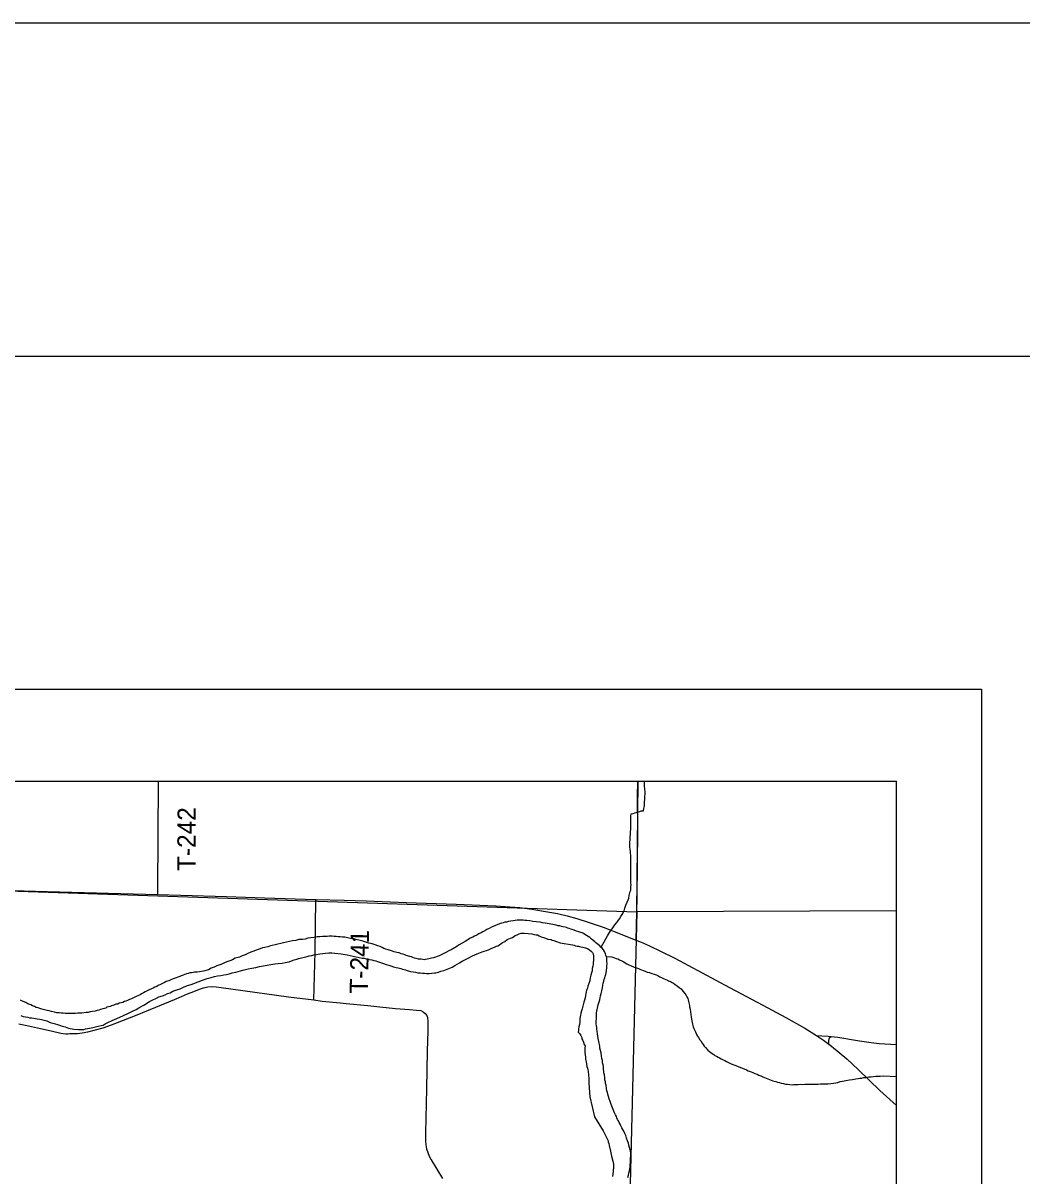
# Model space of a CAD drawing. Extents: x 0 to 68, y 0 to 52.9.
# Drawn here: x 30.062 to 31.562, y 20.269 to 22 of the extents above; entities that cross this region are included whole.
import ezdxf

# ---------------------------------------------------------------- set-up
doc = ezdxf.new("R2010")
doc.units = 0
for name, color, linetype in [('Default', 7, 'Continuous'), ('GM_X_County_Road', 7, 'Continuous'), ('GM_X_Minor_River', 7, 'Continuous'), ('GM_X_State_Route', 7, 'Continuous'), ('GM_X_Township_Road', 7, 'Continuous'), ('GM_X_Township_Road_Text', 7, 'Continuous'), ('SH_Border', 7, 'Continuous'), ('SH_Cut_Line', 7, 'Continuous'), ('SH_Data', 7, 'Continuous')]:
    doc.layers.add(name, color=color, linetype=linetype)

msp = doc.modelspace()

# ---------------------------------------------------------------- linework, layer by layer
at = {"layer": 'Default'}
for p in [(24.6206, 20.8614), (31.3735, 14.1085)]:
    msp.add_line(p, (31.3735, 20.8614), dxfattribs=at)
for points in [[(31.3735, 20.6667), (30.9835, 20.6654), (30.9859, 20.8614)], [(30.868, 20.6442), (30.8655, 20.6446), (30.8625, 20.6454), (30.86, 20.6461), (30.8574, 20.6465), (30.8548, 20.6469), (30.8519, 20.6473), (30.8493, 20.6477), (30.846, 20.6485), (30.8423, 20.6489), (30.8387, 20.6497), (30.8328, 20.6502), (30.8276, 20.651), (30.8229, 20.6518), (30.8185, 20.6522), (30.8155, 20.6526), (30.8129, 20.653), (30.8107, 20.653), (30.8089, 20.653), (30.8071, 20.6531), (30.8041, 20.6531), (30.8012, 20.6524), (30.7982, 20.6521), (30.7938, 20.6514), (30.7908, 20.6507), (30.7882, 20.65), (30.7857, 20.6497), (30.7831, 20.649), (30.7805, 20.6483), (30.7775, 20.6472), (30.7657, 20.6422), (30.762, 20.6405), (30.7583, 20.6387), (30.7557, 20.6369), (30.7527, 20.6354), (30.7498, 20.634), (30.7464, 20.6322), (30.7435, 20.6304), (30.7401, 20.629), (30.7372, 20.6272), (30.7335, 20.6258), (30.7298, 20.6236), (30.7257, 20.6211), (30.7216, 20.6186), (30.7168, 20.6157), (30.7138, 20.6139), (30.712, 20.6125), (30.7097, 20.6114), (30.7075, 20.61), (30.7049, 20.6085), (30.7012, 20.6067), (30.6968, 20.6046), (30.6931, 20.6024), (30.6897, 20.6007), (30.6871, 20.5992), (30.6838, 20.5985), (30.6812, 20.5975), (30.6786, 20.5964), (30.6753, 20.5957), (30.6716, 20.595), (30.669, 20.5943), (30.6665, 20.5936), (30.6642, 20.5933), (30.6624, 20.5937), (30.6591, 20.5941), (30.6558, 20.5945), (30.6521, 20.5953), (30.6499, 20.596), (30.6474, 20.5968), (30.6452, 20.5976), (30.643, 20.5983), (30.6375, 20.5999), (30.6353, 20.6006), (30.6327, 20.6018), (30.6298, 20.6025), (30.6268, 20.6037), (30.6235, 20.6045), (30.6191, 20.6056), (30.6151, 20.6068), (30.6103, 20.6083), (30.607, 20.6095), (30.6037, 20.6106), (30.6012, 20.6117), (30.5982, 20.6132), (30.5946, 20.6144), (30.5909, 20.6159), (30.5862, 20.6174), (30.5814, 20.6186), (30.5766, 20.6201), (30.5722, 20.6213), (30.5663, 20.6228), (30.5619, 20.624), (30.5575, 20.6252), (30.5535, 20.6256), (30.5491, 20.6264), (30.5451, 20.6272), (30.5417, 20.6276), (30.5384, 20.628), (30.5351, 20.628), (30.5322, 20.6284), (30.5292, 20.6285)], [(30.9449, 20.3774), (30.9438, 20.3808), (30.9424, 20.3844), (30.941, 20.3881), (30.9403, 20.3914), (30.9396, 20.394), (30.9389, 20.3966), (30.9382, 20.4003), (30.9375, 20.4051), (30.9368, 20.4076), (30.9365, 20.4102), (30.9358, 20.4132), (30.9355, 20.4165), (30.9351, 20.4205), (30.9344, 20.4235), (30.9341, 20.426), (30.9338, 20.4286), (30.9338, 20.4308), (30.9335, 20.433), (30.9331, 20.4356), (30.9324, 20.4389), (30.9321, 20.4422), (30.9314, 20.4452), (30.9307, 20.4492), (30.93, 20.4536), (30.929, 20.4573), (30.9283, 20.4606), (30.928, 20.4635), (30.9276, 20.4661), (30.9273, 20.468), (30.9269, 20.4705), (30.9259, 20.475), (30.9252, 20.4786), (30.9249, 20.4823), (30.9242, 20.486), (30.9239, 20.4893), (30.9235, 20.4919), (30.9232, 20.4941), (30.9229, 20.4974), (30.9229, 20.5014), (30.923, 20.5051), (30.923, 20.5084), (30.9234, 20.5106), (30.9234, 20.5139), (30.9238, 20.5165), (30.9242, 20.5187), (30.9246, 20.5209), (30.925, 20.5234), (30.9258, 20.5256), (30.9281, 20.5333), (30.9289, 20.5362), (30.9293, 20.5391), (30.9304, 20.5428), (30.9312, 20.5468), (30.932, 20.5512), (30.9328, 20.5552), (30.9332, 20.5585), (30.9343, 20.5611), (30.9347, 20.5637), (30.9355, 20.5662), (30.9363, 20.5688), (30.937, 20.5713), (30.9378, 20.5739), (30.9382, 20.5772), (30.9386, 20.5812), (30.9387, 20.5845), (30.9391, 20.5875), (30.9388, 20.5911), (30.9388, 20.5937), (30.9385, 20.5967), (30.9374, 20.6003), (30.9367, 20.6025), (30.9353, 20.6059), (30.9335, 20.6085), (30.9317, 20.6107), (30.9298, 20.6126), (30.928, 20.6144), (30.9262, 20.6159), (30.9244, 20.6174), (30.9218, 20.6193), (30.92, 20.6211), (30.9156, 20.6245), (30.9131, 20.6267), (30.9109, 20.6282), (30.9083, 20.6297), (30.9058, 20.6316), (30.9036, 20.6327), (30.9018, 20.6338), (30.8996, 20.6346), (30.8966, 20.6354), (30.893, 20.6365), (30.8897, 20.6377), (30.8867, 20.6388), (30.8845, 20.6396), (30.8823, 20.6403), (30.8801, 20.6411), (30.8783, 20.6419), (30.8761, 20.6423), (30.8728, 20.643), (30.8706, 20.6434), (30.868, 20.6442)], [(30.5292, 20.6285), (30.5263, 20.6289), (30.5219, 20.6289), (30.5186, 20.6286), (30.5153, 20.6286), (30.5116, 20.6283), (30.5075, 20.628), (30.5035, 20.6277), (30.499, 20.627), (30.4943, 20.6264), (30.4898, 20.6257), (30.4858, 20.6246), (30.4817, 20.624), (30.4762, 20.6237), (30.4714, 20.6226), (30.4666, 20.6219), (30.4622, 20.6209), (30.4577, 20.6199), (30.4533, 20.6188), (30.4492, 20.6178), (30.4445, 20.6171), (30.4323, 20.614), (30.4293, 20.6129), (30.4249, 20.6119), (30.4216, 20.6112), (30.4182, 20.6101), (30.4149, 20.609), (30.4119, 20.608), (30.4083, 20.6066), (30.4042, 20.6051), (30.3997, 20.603), (30.3953, 20.6009), (30.3912, 20.5991), (30.3868, 20.5973), (30.3805, 20.5956), (30.3764, 20.5934), (30.3727, 20.5916), (30.3694, 20.5906), (30.3653, 20.5891), (30.3616, 20.5874), (30.3576, 20.5859), (30.3531, 20.5842), (30.3487, 20.5824), (30.3446, 20.5806), (30.3405, 20.5785), (30.3383, 20.5778), (30.335, 20.5767), (30.3328, 20.5764), (30.3298, 20.5757), (30.3269, 20.5753), (30.3236, 20.575), (30.3195, 20.5747), (30.3173, 20.5744), (30.3151, 20.574), (30.3125, 20.5737), (30.3099, 20.573), (30.3073, 20.5723), (30.3048, 20.5712), (30.3025, 20.5705), (30.2996, 20.5691), (30.2974, 20.5684), (30.2889, 20.5652), (30.2848, 20.5638), (30.2807, 20.562), (30.277, 20.5606), (30.2744, 20.5591), (30.2715, 20.5577), (30.2681, 20.5563), (30.2648, 20.5549), (30.2626, 20.5534), (30.26, 20.5524), (30.2574, 20.5509), (30.2548, 20.5499), (30.2515, 20.5484), (30.2485, 20.5466), (30.2455, 20.5452), (30.2426, 20.5438), (30.24, 20.5423), (30.2378, 20.5409), (30.2352, 20.5398), (30.2307, 20.5377), (30.2278, 20.5363), (30.2248, 20.5348), (30.2218, 20.5338), (30.2189, 20.5323), (30.2163, 20.5313), (30.2141, 20.5306), (30.2118, 20.5295), (30.2093, 20.5288), (30.2063, 20.5281), (30.2041, 20.527), (30.2015, 20.5267), (30.1985, 20.5253), (30.1967, 20.5246), (30.1948, 20.5242), (30.193, 20.5235), (30.1904, 20.5228), (30.1878, 20.5221), (30.186, 20.521), (30.1841, 20.5203), (30.1819, 20.52)], [(30.632, 20.5794), (30.6342, 20.5786), (30.6361, 20.5782), (30.639, 20.5771), (30.6438, 20.5759), (30.6478, 20.5751), (30.6511, 20.5747), (30.6548, 20.574), (30.6581, 20.5739), (30.6618, 20.5735), (30.6647, 20.5731), (30.668, 20.573), (30.6717, 20.573), (30.6761, 20.5733), (30.6798, 20.5736), (30.682, 20.574), (30.6839, 20.5743), (30.6861, 20.575), (30.6894, 20.5761), (30.6938, 20.5771), (30.7064, 20.5821), (30.7105, 20.5846), (30.7138, 20.5868), (30.7172, 20.5889), (30.7213, 20.5914), (30.7264, 20.5939), (30.7316, 20.5964), (30.7368, 20.5993), (30.7438, 20.6021), (30.7516, 20.6054), (30.7609, 20.6085), (30.766, 20.6107), (30.7701, 20.6124), (30.7731, 20.6139), (30.7749, 20.6146), (30.7775, 20.616), (30.7801, 20.6178), (30.782, 20.6193), (30.7853, 20.6211), (30.789, 20.6239), (30.7938, 20.6257), (30.7968, 20.6271), (30.799, 20.6286), (30.8012, 20.63), (30.8042, 20.6311), (30.8068, 20.6325), (30.8101, 20.6332), (30.8145, 20.6335), (30.8204, 20.6331), (30.8259, 20.6326), (30.8296, 20.6315), (30.8325, 20.6311), (30.8344, 20.6307), (30.8373, 20.6292), (30.8402, 20.628), (30.8435, 20.6269), (30.8465, 20.6258), (30.8501, 20.6246), (30.8549, 20.6238), (30.8567, 20.6231), (30.8593, 20.6223), (30.863, 20.6208), (30.8688, 20.6189), (30.8872, 20.6157), (30.8898, 20.6153), (30.8916, 20.6145), (30.8942, 20.6141), (30.896, 20.6137), (30.8978, 20.6133), (30.8997, 20.6129), (30.9026, 20.6122), (30.9066, 20.6114), (30.9096, 20.6106), (30.9129, 20.6084), (30.9158, 20.6061), (30.9172, 20.6043), (30.9183, 20.6021), (30.9186, 20.5987), (30.9186, 20.5969), (30.9189, 20.5943), (30.9185, 20.5921), (30.9181, 20.5899), (30.9181, 20.5866), (30.9177, 20.5837), (30.9169, 20.5801), (30.9165, 20.5768), (30.9157, 20.5738), (30.9149, 20.5702), (30.9138, 20.5665), (30.913, 20.5618), (30.9115, 20.5577), (30.9103, 20.5537), (30.9095, 20.5508), (30.9088, 20.549), (30.908, 20.5471), (30.9076, 20.5453), (30.9072, 20.5427), (30.9068, 20.5398), (30.906, 20.5361), (30.9049, 20.5329), (30.9041, 20.5299)], [(30.1705, 20.4926), (30.1746, 20.4936), (30.179, 20.4947), (30.182, 20.4954), (30.1853, 20.4972), (30.1894, 20.4993), (30.1957, 20.5022), (30.2027, 20.5054), (30.2127, 20.51), (30.2201, 20.5132), (30.2264, 20.5161), (30.2316, 20.5186), (30.2357, 20.5211), (30.2401, 20.5236), (30.2442, 20.5258), (30.2479, 20.5283), (30.252, 20.5308), (30.2568, 20.5333), (30.2612, 20.5355), (30.2657, 20.5376), (30.2712, 20.5394), (30.2753, 20.5408), (30.279, 20.5426), (30.2827, 20.544), (30.2871, 20.5461), (30.2927, 20.5483), (30.2979, 20.55), (30.3027, 20.5522), (30.309, 20.5546), (30.3145, 20.5564), (30.3315, 20.5628), (30.3382, 20.5653), (30.3444, 20.5667), (30.3496, 20.5681), (30.354, 20.5691), (30.3588, 20.5698), (30.3633, 20.5708), (30.3673, 20.5711), (30.3714, 20.5722), (30.3762, 20.5736), (30.3814, 20.575), (30.3884, 20.5767), (30.3939, 20.5781), (30.3998, 20.5799), (30.4057, 20.5809), (30.4113, 20.5819), (30.4168, 20.5833), (30.4227, 20.5844), (30.4286, 20.5854), (30.4341, 20.5864), (30.44, 20.5871), (30.4452, 20.5877), (30.4511, 20.5884), (30.4555, 20.5891), (30.4588, 20.5897), (30.4614, 20.5904), (30.4651, 20.5919), (30.4692, 20.5933), (30.4729, 20.5943), (30.4762, 20.5954), (30.4803, 20.5964), (30.4847, 20.5975), (30.4884, 20.5982), (30.4917, 20.5992), (30.4954, 20.5999), (30.4987, 20.6006), (30.5028, 20.6013), (30.5076, 20.6023), (30.512, 20.6026), (30.5164, 20.6033), (30.5212, 20.6036), (30.5256, 20.6036), (30.53, 20.6035), (30.5348, 20.6027), (30.5396, 20.6023), (30.5455, 20.6015), (30.5488, 20.6007), (30.5532, 20.5999), (30.5579, 20.5987), (30.5624, 20.5979), (30.5712, 20.596), (30.5741, 20.5956), (30.5759, 20.5952), (30.5781, 20.5944), (30.5822, 20.5936), (30.5858, 20.5932), (30.5888, 20.5921), (30.5917, 20.5917), (30.5943, 20.5909), (30.5972, 20.5898), (30.6001, 20.589), (30.6034, 20.5878), (30.6071, 20.5863), (30.6115, 20.5852), (30.6144, 20.5844), (30.6181, 20.5829), (30.6225, 20.5817), (30.6254, 20.5813), (30.6273, 20.5806), (30.6291, 20.5805), (30.632, 20.5794)], [(30.1819, 20.52), (30.1782, 20.5186), (30.1756, 20.5179), (30.173, 20.5172), (30.1701, 20.5165), (30.1664, 20.5158), (30.1627, 20.5151), (30.1598, 20.5144), (30.1568, 20.5141), (30.1502, 20.5134), (30.1472, 20.5135), (30.1443, 20.5131), (30.1406, 20.5128), (30.1362, 20.5129), (30.1321, 20.5126), (30.1285, 20.513), (30.1251, 20.513), (30.1222, 20.5131), (30.1193, 20.5135), (30.116, 20.5139), (30.1126, 20.5139), (30.1093, 20.5147), (30.1046, 20.5159), (30.1013, 20.5166), (30.098, 20.5174), (30.0939, 20.5182), (30.0903, 20.5194), (30.0873, 20.5201), (30.0844, 20.5213), (30.0815, 20.522), (30.0789, 20.5232), (30.0763, 20.5243), (30.0734, 20.5258), (30.069, 20.5273), (30.0661, 20.5292), (30.0621, 20.5307), (30.058, 20.5326)], [(30.9041, 20.5299), (30.9014, 20.5197), (30.9007, 20.5168), (30.8995, 20.5131), (30.8991, 20.5102), (30.8987, 20.5076), (30.8983, 20.5051), (30.8979, 20.5032), (30.8979, 20.4995), (30.8974, 20.4962), (30.8967, 20.4926), (30.8963, 20.4897), (30.8959, 20.4871), (30.8958, 20.4849), (30.898, 20.4823), (30.8994, 20.4797), (30.9009, 20.4768), (30.9012, 20.4749), (30.9027, 20.472), (30.9037, 20.4697), (30.9048, 20.4664), (30.9059, 20.4642), (30.9058, 20.4609), (30.9058, 20.458), (30.9058, 20.4543), (30.9061, 20.4506), (30.9064, 20.4473), (30.9067, 20.444), (30.9074, 20.44), (30.9081, 20.4366), (30.9088, 20.4333), (30.9095, 20.4308), (30.9102, 20.4282), (30.9105, 20.426), (30.9112, 20.4201), (30.9115, 20.4153), (30.9118, 20.408), (30.913, 20.3874), (30.9204, 20.3576), (30.9333, 20.3368), (30.9405, 20.3217), (30.9409, 20.3199), (30.9416, 20.3173), (30.9423, 20.3143), (30.944, 20.3062), (30.9457, 20.2985), (30.9475, 20.2911), (30.9485, 20.2864), (30.9485, 20.2831), (30.9485, 20.2801), (30.9484, 20.2783), (30.948, 20.2761), (30.9476, 20.2713), (30.9472, 20.268)], [(30.0585, 20.5095), (30.0622, 20.5083), (30.0658, 20.5076), (30.0691, 20.5072), (30.0717, 20.5064), (30.0746, 20.506), (30.0783, 20.5056), (30.0831, 20.5048), (30.0871, 20.504), (30.0897, 20.5036), (30.0974, 20.5016), (30.0996, 20.5009), (30.1025, 20.4994), (30.1088, 20.4975), (30.115, 20.4955), (30.1183, 20.4948), (30.1209, 20.4936), (30.1231, 20.4932), (30.1253, 20.4925), (30.13, 20.4909), (30.1381, 20.4894), (30.1451, 20.4885), (30.1488, 20.4885), (30.1506, 20.4885), (30.1532, 20.4888), (30.1558, 20.4899), (30.1617, 20.4909), (30.1665, 20.4919), (30.1705, 20.4926)], [(30.9704, 20.2666), (30.9711, 20.2699), (30.9719, 20.2732), (30.9727, 20.2765), (30.9731, 20.2798), (30.9735, 20.2816), (30.9739, 20.2849), (30.9743, 20.2897), (30.9744, 20.2952), (30.9748, 20.2996), (30.9745, 20.3029), (30.9742, 20.3062), (30.9735, 20.3081), (30.9728, 20.3117), (30.9717, 20.315), (30.971, 20.318), (30.9696, 20.3217), (30.9682, 20.3257), (30.9671, 20.3294), (30.9657, 20.3324), (30.9642, 20.3361), (30.9628, 20.3387), (30.9614, 20.3412), (30.9599, 20.3442), (30.9585, 20.3468), (30.9574, 20.349), (30.956, 20.3516), (30.9549, 20.3538), (30.9538, 20.356), (30.9531, 20.3582), (30.9517, 20.3608), (30.9502, 20.3638), (30.9463, 20.3737), (30.9449, 20.3774)]]:
    msp.add_lwpolyline(points, dxfattribs=at)
msp.add_lwpolyline([(30.0241, 20.6975), (30.9835, 20.6654), (30.9602, 19.7051), (30.0095, 19.7364)], close=True, dxfattribs=at)
at = {"layer": 'GM_X_County_Road'}
for points in [[(31.2534, 20.4799), (31.2617, 20.4794), (31.2712, 20.4788), (31.2758, 20.4783)], [(31.272, 20.4669), (31.272, 20.4715), (31.2722, 20.4734), (31.2725, 20.4744), (31.2733, 20.4762), (31.2758, 20.4783)], [(31.2758, 20.4783), (31.2856, 20.4772), (31.3181, 20.4718), (31.3359, 20.469), (31.3478, 20.4676), (31.3735, 20.466)]]:
    msp.add_lwpolyline(points, dxfattribs=at)
at = {"layer": 'GM_X_Minor_River'}
for points in [[(30.93, 20.6124), (30.9396, 20.6293), (30.9411, 20.6319), (30.9426, 20.6344), (30.9445, 20.6373), (30.9467, 20.6399), (30.9486, 20.6428), (30.9505, 20.646), (30.9535, 20.6493), (30.9554, 20.6515), (30.9576, 20.6551), (30.9599, 20.6584), (30.9617, 20.6613), (30.9632, 20.6639), (30.9647, 20.6668), (30.9659, 20.6708), (30.9674, 20.6756), (30.969, 20.6799), (30.9705, 20.6832), (30.9716, 20.6861), (30.9724, 20.6898), (30.9736, 20.6957), (30.9747, 20.6979), (30.9747, 20.7008), (30.9748, 20.7034), (30.9752, 20.7059), (30.9749, 20.7092), (30.9749, 20.7136), (30.9746, 20.7184), (30.9747, 20.7224), (30.9747, 20.7272), (30.9748, 20.7324), (30.9748, 20.7375), (30.9749, 20.7441), (30.9746, 20.7481), (30.9746, 20.7507), (30.9743, 20.7533), (30.974, 20.7562), (30.9737, 20.7595), (30.9733, 20.7625), (30.9734, 20.7661), (30.9734, 20.7698), (30.9738, 20.7735), (30.9744, 20.7859), (30.9748, 20.7892), (30.9748, 20.7926), (30.9748, 20.7962), (30.9749, 20.8003), (30.9746, 20.8043), (30.9746, 20.8072), (30.9747, 20.8098), (30.9754, 20.8124), (30.978, 20.8131), (30.9806, 20.8141), (30.9828, 20.8145), (30.9854, 20.8155), (30.988, 20.8162), (30.9902, 20.8169), (30.992, 20.8173), (30.9939, 20.8173), (30.9943, 20.8206), (30.9947, 20.8228), (30.9951, 20.825), (30.9951, 20.8272), (30.9955, 20.8294), (30.9955, 20.8312), (30.9956, 20.8334), (30.996, 20.8356), (30.9961, 20.8455), (30.9958, 20.8495), (30.9955, 20.8547), (30.9955, 20.858), (30.9951, 20.8614)], [(30.938, 20.5984), (30.9458, 20.5977), (30.9477, 20.5973), (30.9502, 20.5965), (30.9528, 20.5954), (30.9554, 20.5946), (30.9579, 20.5931), (30.9612, 20.5916), (30.9641, 20.5904), (30.9663, 20.5889), (30.9689, 20.5874), (30.9715, 20.5859), (30.974, 20.5848), (30.9795, 20.5825), (30.9832, 20.5814), (30.9861, 20.5802), (30.9883, 20.5791), (30.9909, 20.5783), (30.9934, 20.5772), (30.9964, 20.5764), (30.9993, 20.5749), (31.003, 20.5741), (31.0063, 20.573), (31.0096, 20.5719), (31.0128, 20.5707), (31.0154, 20.5696), (31.0183, 20.5677), (31.022, 20.5662), (31.0249, 20.5647), (31.0275, 20.5639), (31.0297, 20.5628), (31.0315, 20.562), (31.0341, 20.5609), (31.0366, 20.5594), (31.0388, 20.5583), (31.0414, 20.5564), (31.0443, 20.5545), (31.0472, 20.5519), (31.0501, 20.5497), (31.053, 20.5463), (31.0556, 20.5426), (31.0574, 20.5408), (31.0588, 20.5378), (31.0602, 20.5352), (31.0606, 20.5334), (31.0613, 20.5308), (31.0616, 20.5286), (31.0623, 20.5268), (31.0627, 20.5249), (31.063, 20.5227), (31.0637, 20.5194), (31.0654, 20.5073), (31.0664, 20.5017), (31.0675, 20.4966), (31.0685, 20.4929), (31.0696, 20.4903), (31.0707, 20.4874), (31.0718, 20.4852), (31.0728, 20.4829), (31.0735, 20.4811), (31.075, 20.4789), (31.0764, 20.4766), (31.0786, 20.4733), (31.0797, 20.4715), (31.0818, 20.4681), (31.0833, 20.4663), (31.0851, 20.4637), (31.0869, 20.4618), (31.0905, 20.4577), (31.0931, 20.4555), (31.0949, 20.454), (31.0971, 20.4525), (31.0993, 20.451), (31.1011, 20.4499), (31.1033, 20.4488), (31.1059, 20.4473), (31.1081, 20.4461), (31.1106, 20.4446), (31.1132, 20.4431), (31.1161, 20.442), (31.1183, 20.4405), (31.1212, 20.4394), (31.1242, 20.4378), (31.1278, 20.4363), (31.1322, 20.4348), (31.137, 20.4329), (31.141, 20.4314), (31.145, 20.4295), (31.1483, 20.4284), (31.1512, 20.4268), (31.1553, 20.4253), (31.1582, 20.4242), (31.1611, 20.4227), (31.1644, 20.4215), (31.167, 20.4204), (31.1699, 20.4193), (31.1728, 20.4178), (31.1831, 20.4136)], [(31.1831, 20.4136), (31.1857, 20.4128), (31.1882, 20.4117), (31.1923, 20.4105), (31.1952, 20.4097), (31.1981, 20.409), (31.2007, 20.4082), (31.204, 20.4074), (31.2069, 20.4067), (31.2102, 20.4066), (31.2136, 20.4062), (31.2169, 20.4058), (31.2194, 20.4061), (31.222, 20.4061), (31.2261, 20.406), (31.2294, 20.4064), (31.2327, 20.4063), (31.236, 20.4066), (31.2393, 20.4066), (31.2426, 20.4066), (31.2459, 20.4065), (31.2489, 20.4068), (31.2526, 20.4068), (31.2562, 20.4067), (31.2596, 20.4071), (31.2629, 20.407), (31.2677, 20.4073), (31.2713, 20.4073), (31.275, 20.4076), (31.2791, 20.4079), (31.2824, 20.4086), (31.2857, 20.4093), (31.289, 20.4104), (31.2927, 20.411), (31.2975, 20.4121), (31.3031, 20.4131), (31.3075, 20.4138), (31.3127, 20.4144), (31.316, 20.4151), (31.3189, 20.4155), (31.3215, 20.4158), (31.3241, 20.4165), (31.3278, 20.4168), (31.3322, 20.4175), (31.3359, 20.4178), (31.3429, 20.4185), (31.3458, 20.4188), (31.3491, 20.4187), (31.3543, 20.419), (31.3735, 20.4181)]]:
    msp.add_lwpolyline(points, dxfattribs=at)
at = {"layer": 'GM_X_State_Route'}
for points in [[(29.7888, 20.706), (29.9151, 20.7019), (29.975, 20.6995), (30.029, 20.6978), (30.0979, 20.6959), (30.2644, 20.6913), (30.2987, 20.6903), (30.3676, 20.6884), (30.4246, 20.6866), (30.5016, 20.6841)], [(30.5016, 20.6841), (30.5444, 20.6827), (30.5774, 20.6817), (30.6373, 20.6795), (30.7122, 20.6769), (30.7721, 20.6744), (30.7931, 20.6731), (30.808, 20.6717), (30.8259, 20.6694), (30.8496, 20.6655), (30.8644, 20.6627), (30.879, 20.6593), (30.8935, 20.6554), (30.9107, 20.6501), (30.9334, 20.6422), (30.9586, 20.6326), (30.9823, 20.6231), (30.9892, 20.6203), (31.003, 20.6143), (31.0193, 20.6066), (31.0407, 20.5957), (31.1227, 20.552), (31.1729, 20.5251), (31.2073, 20.5066), (31.2361, 20.4905), (31.2534, 20.4799), (31.264, 20.4728), (31.272, 20.4669), (31.276, 20.4639), (31.2877, 20.4544), (31.299, 20.4445), (31.3165, 20.4281), (31.3489, 20.3969), (31.3735, 20.3747)]]:
    msp.add_lwpolyline(points, dxfattribs=at)
at = {"layer": 'GM_X_Township_Road'}
for points in [[(30.2644, 20.6913), (30.2645, 20.6986), (30.2652, 20.8614)], [(30.9846, 20.8614), (30.9842, 20.8386), (30.9845, 20.7876), (30.9835, 20.6868), (30.9823, 20.6231)], [(30.4985, 20.5331), (30.5007, 20.6054), (30.5016, 20.6841)], [(30.0558, 20.4973), (30.0701, 20.4943), (30.0836, 20.4914), (30.104, 20.4866), (30.1185, 20.4834), (30.126, 20.4823), (30.1292, 20.4822), (30.1321, 20.4825), (30.1439, 20.4828), (30.1506, 20.4836), (30.1594, 20.4854), (30.1708, 20.4883), (30.1824, 20.4913), (30.1949, 20.4955), (30.2308, 20.5096), (30.2811, 20.5304), (30.2892, 20.534), (30.2997, 20.5383), (30.3088, 20.5421), (30.3185, 20.5459), (30.3268, 20.5491), (30.3331, 20.5513), (30.3395, 20.5527), (30.3451, 20.5534), (30.3522, 20.5527), (30.3597, 20.5516), (30.3921, 20.5475), (30.4607, 20.5379), (30.4985, 20.5331)], [(30.4985, 20.5331), (30.5112, 20.5315), (30.538, 20.5288), (30.547, 20.5276), (30.5796, 20.5246), (30.5976, 20.5228), (30.6213, 20.5201), (30.6424, 20.5186), (30.653, 20.5179), (30.6595, 20.5171), (30.6626, 20.5153), (30.6659, 20.5128), (30.6682, 20.5098), (30.6692, 20.5066), (30.6698, 20.5006), (30.6699, 20.4864), (30.669, 20.4565), (30.668, 20.3995), (30.6664, 20.3335), (30.6665, 20.3215), (30.6669, 20.3156), (30.6679, 20.3097), (30.6697, 20.3039), (30.6721, 20.2985), (30.6749, 20.2932), (30.6918, 20.2648)]]:
    msp.add_lwpolyline(points, dxfattribs=at)
at = {"layer": 'SH_Border'}
msp.add_lwpolyline([(2, 21.5), (33.5, 21.5), (33.5, 0.5), (2, 0.5)], close=True, dxfattribs=at)
at = {"layer": 'SH_Cut_Line'}
msp.add_lwpolyline([(0, 0), (34, 0), (34, 22), (0, 22)], close=True, dxfattribs=at)
at = {"layer": 'SH_Data'}
for p, q in [((24.5015, 21), (31.5015, 21)), ((31.5015, 21), (31.5015, 14))]:
    msp.add_line(p, q, dxfattribs=at)

# ---------------------------------------------------------------- texts
at = {"layer": 'GM_X_Township_Road_Text'}
for s, rotation, p in [('T-242', 89.7193, (30.3209, 20.7267)), ('T-241', 88.8768, (30.5798, 20.5424))]:
    msp.add_text(s, height=0.02741, rotation=rotation, dxfattribs=at).set_placement(p)

doc.saveas('drawing.dxf')
